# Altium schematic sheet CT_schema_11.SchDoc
size 274 x 160 mm
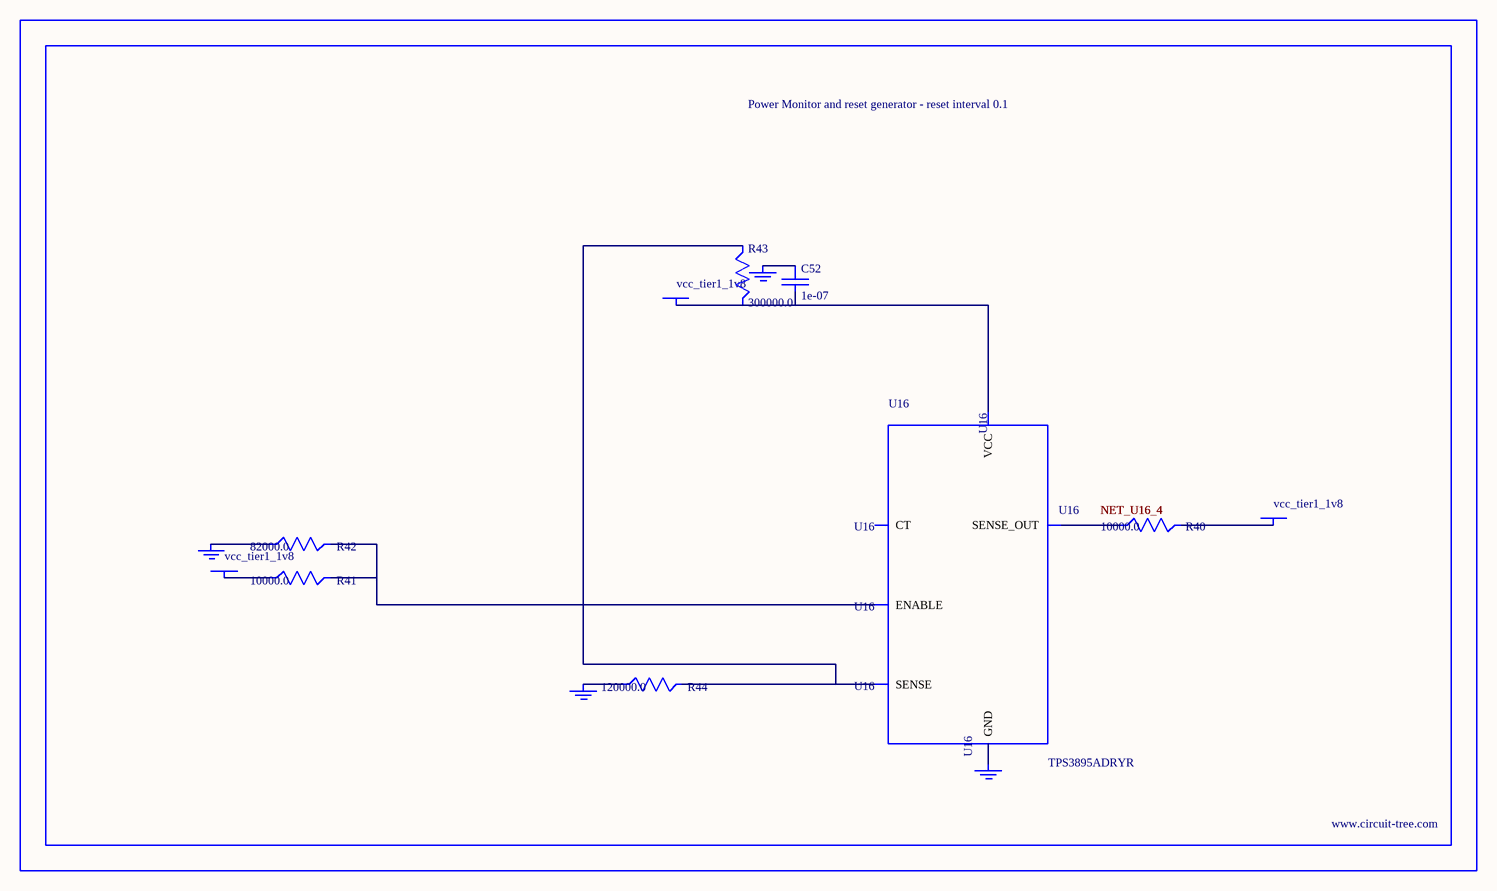
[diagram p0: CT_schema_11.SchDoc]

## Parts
BORDER10  (no value)
C52  1e-07  [C0402]
GND_INSTANCE_10_0  (no value)
GND_INSTANCE_10_1  (no value)
GND_INSTANCE_10_2  (no value)
GND_INSTANCE_10_3  (no value)
POWER_INSTANCE_10_0  vcc_tier1_1v8
POWER_INSTANCE_10_1  vcc_tier1_1v8
POWER_INSTANCE_10_2  vcc_tier1_1v8
R40  10000.0  [R0603]
R41  10000.0  [R0603]
R42  82000.0  [R0603]
R43  300000.0  [R0603]
R44  120000.0  [R0603]
U16  TPS3895ADRYR  [SON-6]

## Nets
NetC52_1: C52.1 GND_INSTANCE_10_2.0(GND)
NetC52_2: C52.2 POWER_INSTANCE_10_2.0(PWR) R43.2 U16.6(VCC)
NetGND_INSTANCE_10_0_0: GND_INSTANCE_10_0.0(GND) R42.1
NetGND_INSTANCE_10_1_0: GND_INSTANCE_10_1.0(GND) R44.1
NetGND_INSTANCE_10_3_0: GND_INSTANCE_10_3.0(GND) U16.2(GND)
NetPOWER_INSTANCE_10_0_0: POWER_INSTANCE_10_0.0(PWR) R41.1
NetPOWER_INSTANCE_10_1_0: POWER_INSTANCE_10_1.0(PWR) R40.2
NetR40_1: R40.1 U16.4(SENSE_OUT)
NetR41_2: R41.2 R42.2 U16.1(ENABLE)
NetR43_1: R43.1 R44.2 U16.3(SENSE)

Not connected (* = marked no-connect by the designer): U16 5(CT)

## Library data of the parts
BORDER10 = BORDER_PAGE10
C52 = C0402C104K3RACTU
GND_INSTANCE_10_0-GND_INSTANCE_10_3 = GND
POWER_INSTANCE_10_0-POWER_INSTANCE_10_2 = PWR
R40 R41 = RC0603JR-0710KL
R42 = RC0603JR-0782KL
R43 = RC0603JR-07300KL
R44 = RC0603JR-07120KL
